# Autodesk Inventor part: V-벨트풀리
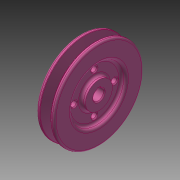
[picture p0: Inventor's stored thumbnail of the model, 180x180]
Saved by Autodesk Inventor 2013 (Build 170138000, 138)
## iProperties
Created: 2015-09
Part Number: V-벨트풀리
Material: 강철, 연강
Document SubType Name: Modeling
Designer: mduedu
Density: 1 g/cm^3
Author: mduedu
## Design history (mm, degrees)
sketch "스케치1"
  geometry: L1 (-10, 0)-(10, 0); L2 (-10, 0)-(-10, 50); L3 (-10, 50)-(-5.976, 50); L4 (-5.976, 50)-(-2.154, 37.5); L5 (-2.154, 37.5)-(2.154, 37.5); L6 (2.154, 37.5)-(5.976, 50); L7 (5.976, 50)-(10, 50); L8 (10, 50)-(10, 0); L9 (0, 0)-(0, 37.5); L10 (-10, 45.5)-(10, 45.5); 3 further points
  constraints: 20 end point, 6 point on line, 3 perpendicular, 2 midpoint, 2 parallel, 2 symmetric about line, 1 coincident, 1 collinear, 1 equal length, 1 horizontal, 1 vertical, 1 vertical alignment
  dimensions: "d0" = 20 distance between parallel lines of L8 L2; "d2" = 100 diameter of L3 L1; "d5" = 8 distance between parallel lines of L5 L10; "d6" = 9.2 distance of point (4.6, 45.5) point (-4.6, 45.5); "d7" = 34 deg angle of L6 L4; "d40" = 4.5 distance between parallel lines of L10 L3
revolve "회전1" sketch "스케치1" stored, may be unused: angle "d8" = 90 deg
sketch "스케치2"
  geometry: C1 r 15 at (0, 0); C2 r 30 at (0, 0); 1 further point
  constraints: 2 centre point, 2 coincident
  dimensions: "d9" = 30 diameter of C1; "d41" = 60 diameter of C2
extrude "돌출5" cut sketch "스케치2" distance "d42" = 5; taper "d43" = 0 deg
hole "구멍2" diameter "d46" = 12; stored, may be unused: countersink angle "d50" = 90 deg, drill point angle "d52" = 118 deg; dims "d44" = 10, "d45" = 10, "d47" = 6, "d48" = 4, "d49" = 2, "d51" = 8
sketch "스케치8"
  geometry: L1 (-2, 5.657)-(2, 5.657); L2 (2, 5.657)-(2, 7.8); L3 (2, 7.8)-(-2, 7.8); L4 (-2, 7.8)-(-2, 5.657); A1 r 6 centre (0, 0) between (-2, 5.657) and (2, 5.657) reference; 1 further point
  constraints: 8 end point, 2 parallel, 2 point on circle, 1 horizontal, 1 perpendicular
  dimensions: "d53" = 4 distance of L2.end L3.end; "d55" = 13.8 dimension on A1 L3
extrude "돌출6" cut sketch "스케치8" stored distance "d56" = 5; taper "d57" = 0 deg
sketch "스케치9"
  geometry: C1 r 3 at (0, 22.5); 1 further point
  constraints: 1 centre point, 1 vertical alignment
  dimensions: "d61" = 6 diameter of C1; "d62" = 22.5 distance of C1.centre point (0, 0)
extrude "돌출7" cut sketch "스케치9" stored distance "d63" = 5; taper "d64" = 0 deg
chamfer "모따기3" distance "d65" = 1; stored, may be unused: second distance "d66" = 2, angle "d67" = 45 deg
fillet "모깎기5" dims "d71" = 2, "d72" = 1, "d73" = 0.5
fillet "모깎기6" dims "d74" = 3
fillet "모깎기7" dims "d75" = 3
fillet "모깎기8" dims "d76" = 3
chamfer "모따기4" distance "d82" = 1; stored, may be unused: second distance "d83" = 2, angle "d84" = 45 deg
node "솔리드1"
mirror "대칭2"
pattern_circular "원형 패턴1" dims "d69" = 360 deg
